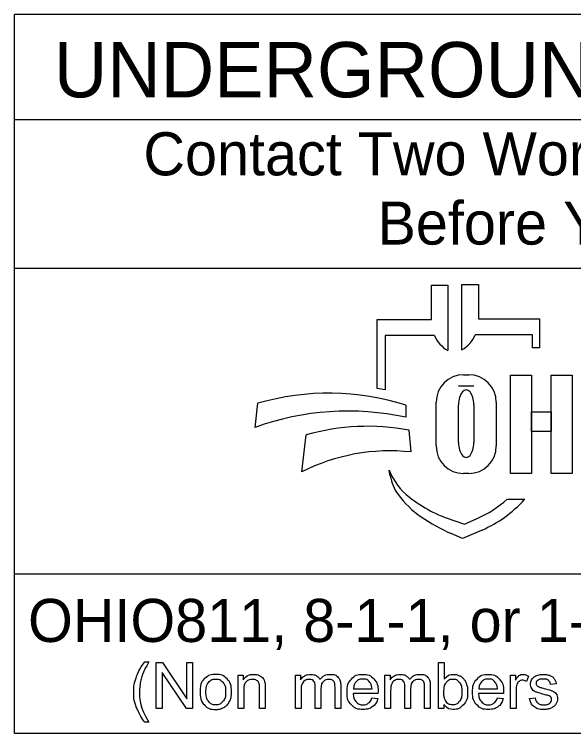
# Model space of a CAD drawing. Extents: x -4 to 116, y -17 to 29.
# Drawn here: x 50.861 to 52.679, y -12.463 to -10.125 of the extents above; entities that cross this region are included whole.
import ezdxf

# ---------------------------------------------------------------- set-up
doc = ezdxf.new("R2010")
doc.units = 0
doc.layers.add('SH_Data', color=7, linetype='Continuous')
doc.layers.add('SH_Text', color=7, linetype='Continuous')

msp = doc.modelspace()

# ---------------------------------------------------------------- linework, layer by layer
at = {"layer": 'SH_Data'}
for p, q in [((50.8608, -12.4625), (50.8608, -10.125)), ((55.1108, -10.125), (50.8608, -10.125)), ((50.8608, -10.4666), (55.1108, -10.4666)), ((50.8608, -10.95), (55.1108, -10.95)), ((55.1108, -11.9447), (50.8608, -11.9447)), ((55.1108, -12.4625), (50.8608, -12.4625))]:
    msp.add_line(p, q, dxfattribs=at)
at = {"layer": 'SH_Text'}
for p, q in [((52.2168, -11.117), (52.2168, -11.0055)), ((52.2168, -11.0055), (52.2705, -11.0055)), ((52.2705, -11.0055), (52.2705, -11.2176)), ((52.3161, -11.2153), (52.3161, -11.0032)), ((52.3161, -11.0032), (52.3698, -11.0032)), ((52.3698, -11.0032), (52.3698, -11.1147)), ((52.0409, -11.3409), (52.0409, -11.117)), ((52.0409, -11.117), (52.2168, -11.117)), ((52.3698, -11.1147), (52.569, -11.1147)), ((52.569, -11.1147), (52.569, -11.2085)), ((52.0661, -11.1685), (52.0661, -11.3453)), ((52.2272, -11.1685), (52.0661, -11.1685)), ((52.5457, -11.1661), (52.3594, -11.1661)), ((52.5457, -11.2085), (52.5457, -11.1661)), ((52.569, -11.2085), (52.5457, -11.2085)), ((52.3218, -11.2962), (52.3384, -11.2962)), ((52.3551, -11.3332), (52.3053, -11.3332)), ((51.6435, -11.4672), (51.6529, -11.3891)), ((52.1342, -11.3956), (52.1342, -11.4344)), ((52.2324, -11.5277), (52.2324, -11.3857)), ((52.3053, -11.5163), (52.3053, -11.394)), ((52.3551, -11.394), (52.3551, -11.5163)), ((52.4278, -11.3857), (52.4278, -11.5277)), ((52.1441, -11.4762), (52.1504, -11.5471)), ((51.7953, -11.6117), (51.81, -11.4916)), ((52.083, -11.6246), (52.08, -11.6067)), ((52.3384, -11.6172), (52.3218, -11.6172)), ((52.4633, -11.7005), (52.5207, -11.7005)), ((52.2649, -11.7609), (52.3243, -11.7814)), ((52.3243, -11.7814), (52.3653, -11.7636)), ((52.3816, -11.8009), (52.3183, -11.8284)), ((52.3183, -11.8284), (52.2809, -11.812))]:
    msp.add_line(p, q, dxfattribs=at)
for points in [[(52.4743, -11.2972), (52.5422, -11.2972), (52.5422, -11.6172), (52.4743, -11.6172)], [(52.6064, -11.2972), (52.6744, -11.2972), (52.6744, -11.6172), (52.6064, -11.6172)], [(52.5422, -11.4171), (52.6064, -11.4171), (52.6064, -11.4811), (52.5422, -11.4811)]]:
    msp.add_lwpolyline(points, close=True, dxfattribs=at)
for points in [[(51.2854, -12.2287), (51.2986, -12.2287)], [(51.3222, -12.3814), (51.3222, -12.2312), (51.3425, -12.2312), (51.4215, -12.3492), (51.4215, -12.2312), (51.4405, -12.2312), (51.4405, -12.3814), (51.4202, -12.3814), (51.3412, -12.2635), (51.3412, -12.3814), (51.3222, -12.3814)], [(52.2576, -12.3814), (52.2406, -12.3814), (52.2406, -12.2312), (52.259, -12.2312), (52.259, -12.2848)], [(51.5881, -12.3814), (51.5881, -12.2726), (51.6047, -12.2726), (51.6047, -12.288)], [(51.7745, -12.3814), (51.7745, -12.2726), (51.791, -12.2726), (51.791, -12.2879)], [(52.0659, -12.3814), (52.0659, -12.2726), (52.0824, -12.2726), (52.0824, -12.2879)], [(52.4737, -12.3814), (52.4737, -12.2726), (52.4903, -12.2726), (52.4903, -12.289)], [(52.5327, -12.276), (52.5263, -12.2931)], [(51.6765, -12.3145), (51.6765, -12.3814), (51.6581, -12.3814), (51.6581, -12.3153)], [(51.8576, -12.3182), (51.8576, -12.3814), (51.8392, -12.3814), (51.8392, -12.3107)], [(51.9221, -12.3067), (51.9221, -12.3814), (51.9036, -12.3814), (51.9036, -12.3129)], [(51.9632, -12.3166), (52.0239, -12.3166)], [(52.149, -12.3182), (52.149, -12.3814), (52.1306, -12.3814), (52.1306, -12.3107)], [(52.2134, -12.3067), (52.2134, -12.3814), (52.195, -12.3814), (52.195, -12.3129)], [(52.3711, -12.3166), (52.4319, -12.3166)], [(52.6227, -12.3007), (52.6046, -12.3031)], [(51.6066, -12.322), (51.6066, -12.3814), (51.5881, -12.3814)], [(51.793, -12.325), (51.793, -12.3814), (51.7745, -12.3814)], [(52.0433, -12.3317), (51.9621, -12.3317)], [(52.0843, -12.325), (52.0843, -12.3814), (52.0659, -12.3814)], [(52.4513, -12.3317), (52.3701, -12.3317)], [(52.4921, -12.3244), (52.4921, -12.3814), (52.4737, -12.3814)], [(52.0237, -12.3463), (52.0428, -12.3487)], [(52.4317, -12.3463), (52.4508, -12.3487)], [(52.5363, -12.3489), (52.5545, -12.346)], [(52.2576, -12.3678), (52.2576, -12.3814)], [(51.2986, -12.4256), (51.2854, -12.4256)]]:
    msp.add_lwpolyline(points, dxfattribs=at)
for centre, radius, start, end in [((52.3186, -11.1317), 0.0985, 201.9296, 240.7469), ((52.268, -11.1294), 0.0985, 299.2531, 338.0704), ((52.3218, -11.3857), 0.0895, 90, 180), ((52.3384, -11.3857), 0.0895, 0, 90), ((51.883, -12.1752), 0.8191, 72.1402, 106.3144), ((51.9127, -12.1499), 0.8191, 79.2074, 81.0007), ((51.946, -12.3063), 0.8919, 77.8238, 109.8274), ((52.01, -12.196), 0.7322, 79.44, 105.8467), ((52.082, -12.1792), 0.6357, 83.8248, 116.8021), ((52.3218, -11.5277), 0.0895, 180, 270), ((52.3384, -11.5277), 0.0895, 270, 0), ((52.2674, -11.5346), 0.2008, 201.0457, 232.5314), ((52.2243, -11.6005), 0.1433, 189.6817, 216.0884), ((52.358, -11.5031), 0.3088, 216.0884, 235.7167), ((52.4599, -11.2834), 0.5173, 232.5314, 241.794), ((52.2219, -11.4331), 0.3602, 293.4582, 312.0712), ((52.2219, -11.4331), 0.401, 293.4582, 317.8286), ((52.3747, -11.4422), 0.3371, 241.794, 250.9821), ((52.5245, -11.2588), 0.6044, 235.7167, 246.2325)]:
    msp.add_arc(centre, radius, start, end, dxfattribs=at)
for centre, start_param, end_param in [((52.3302, -11.394), 4.712389, 7.853982), ((52.3302, -11.5163), 1.570796, 4.712389)]:
    msp.add_ellipse(centre, major_axis=(0, 0.0484), ratio=0.514403, start_param=start_param, end_param=end_param, dxfattribs=at)
for points in [[(51.2854, -12.4256), (51.2701, -12.4063), (51.2596, -12.3805), (51.249, -12.3547), (51.249, -12.327), (51.249, -12.3027), (51.2569, -12.2803), (51.2661, -12.2544), (51.2854, -12.2287)], [(51.2986, -12.2287), (51.2862, -12.25), (51.2822, -12.2591), (51.276, -12.2733), (51.2724, -12.2886), (51.268, -12.3078), (51.268, -12.3271), (51.268, -12.3764), (51.2986, -12.4256)], [(51.4646, -12.327), (51.4646, -12.2968), (51.4814, -12.2822), (51.4955, -12.2702), (51.5156, -12.2702), (51.538, -12.2702), (51.5523, -12.2848), (51.5665, -12.2995), (51.5665, -12.3254), (51.5665, -12.3464), (51.5602, -12.3585), (51.5539, -12.3705), (51.5419, -12.3771), (51.5298, -12.3838), (51.5156, -12.3838), (51.4928, -12.3838), (51.4787, -12.3692), (51.4646, -12.3545), (51.4646, -12.327)], [(51.6047, -12.288), (51.6167, -12.2702), (51.6393, -12.2702), (51.6491, -12.2702), (51.6574, -12.2737), (51.6656, -12.2772), (51.6697, -12.283), (51.6738, -12.2887), (51.6755, -12.2966), (51.6765, -12.3017), (51.6765, -12.3145)], [(51.791, -12.2879), (51.7961, -12.2799), (51.8046, -12.275), (51.8131, -12.2702), (51.824, -12.2702), (51.8361, -12.2702), (51.8438, -12.2752), (51.8516, -12.2802), (51.8548, -12.2892), (51.8677, -12.2702), (51.8884, -12.2702), (51.9046, -12.2702), (51.9133, -12.2791), (51.9221, -12.2881), (51.9221, -12.3067)], [(52.0428, -12.3487), (52.0383, -12.3654), (52.0261, -12.3746), (52.0139, -12.3838), (51.9949, -12.3838), (51.9711, -12.3838), (51.9571, -12.3691), (51.9431, -12.3544), (51.9431, -12.3279), (51.9431, -12.3005), (51.9573, -12.2853), (51.9714, -12.2702), (51.9939, -12.2702), (52.0157, -12.2702), (52.0296, -12.285), (52.0434, -12.2999), (52.0434, -12.3268), (52.0434, -12.3284), (52.0433, -12.3317)], [(52.0824, -12.2879), (52.0875, -12.2799), (52.096, -12.275), (52.1045, -12.2702), (52.1154, -12.2702), (52.1275, -12.2702), (52.1352, -12.2752), (52.1429, -12.2802), (52.1461, -12.2892), (52.1591, -12.2702), (52.1798, -12.2702), (52.196, -12.2702), (52.2047, -12.2791), (52.2134, -12.2881), (52.2134, -12.3067)], [(52.259, -12.2848), (52.2707, -12.2702), (52.2888, -12.2702), (52.2988, -12.2702), (52.3078, -12.2742), (52.3167, -12.2782), (52.3225, -12.2856), (52.3283, -12.2929), (52.3316, -12.3032), (52.3349, -12.3136), (52.3349, -12.3253), (52.3349, -12.3533), (52.321, -12.3685), (52.3072, -12.3838), (52.2878, -12.3838), (52.2686, -12.3838), (52.2576, -12.3678)], [(52.4508, -12.3487), (52.4463, -12.3654), (52.4341, -12.3746), (52.4219, -12.3838), (52.4029, -12.3838), (52.3791, -12.3838), (52.3651, -12.3691), (52.3511, -12.3544), (52.3511, -12.3279), (52.3511, -12.3005), (52.3653, -12.2853), (52.3794, -12.2702), (52.4019, -12.2702), (52.4237, -12.2702), (52.4375, -12.285), (52.4514, -12.2999), (52.4514, -12.3268), (52.4514, -12.3284), (52.4513, -12.3317)], [(52.4903, -12.289), (52.4966, -12.2775), (52.502, -12.2738), (52.5074, -12.2702), (52.5138, -12.2702), (52.5231, -12.2702), (52.5327, -12.276)], [(52.5545, -12.346), (52.556, -12.357), (52.5631, -12.3628), (52.5701, -12.3687), (52.5827, -12.3687), (52.5955, -12.3687), (52.6017, -12.3635), (52.6078, -12.3583), (52.6078, -12.3514), (52.6078, -12.3451), (52.6024, -12.3415), (52.5986, -12.339), (52.5835, -12.3352), (52.5632, -12.3301), (52.5553, -12.3264), (52.5475, -12.3227), (52.5434, -12.3161), (52.5394, -12.3095), (52.5394, -12.3015), (52.5394, -12.2942), (52.5427, -12.288), (52.5461, -12.2818), (52.5518, -12.2777), (52.5561, -12.2746), (52.5635, -12.2724), (52.571, -12.2702), (52.5795, -12.2702), (52.5923, -12.2702), (52.602, -12.2738), (52.6117, -12.2775), (52.6163, -12.2838), (52.621, -12.2901), (52.6227, -12.3007)], [(51.4836, -12.327), (51.4836, -12.3479), (51.4927, -12.3583), (51.5018, -12.3687), (51.5156, -12.3687), (51.5293, -12.3687), (51.5384, -12.3582), (51.5475, -12.3478), (51.5475, -12.3264), (51.5475, -12.3062), (51.5384, -12.2958), (51.5292, -12.2854), (51.5156, -12.2854), (51.5018, -12.2854), (51.4927, -12.2957), (51.4836, -12.3061), (51.4836, -12.327)], [(51.6581, -12.3153), (51.6581, -12.304), (51.6559, -12.2984), (51.6537, -12.2928), (51.6483, -12.2895), (51.6428, -12.2862), (51.6354, -12.2862), (51.6236, -12.2862), (51.6151, -12.2937), (51.6066, -12.3011), (51.6066, -12.322)], [(51.8392, -12.3107), (51.8392, -12.2985), (51.8347, -12.2923), (51.8302, -12.2862), (51.8199, -12.2862), (51.8121, -12.2862), (51.8055, -12.2903), (51.7989, -12.2944), (51.7959, -12.3022), (51.793, -12.3101), (51.793, -12.325)], [(51.9036, -12.3129), (51.9036, -12.3018), (51.9018, -12.297), (51.9, -12.2921), (51.8953, -12.2891), (51.8906, -12.2862), (51.8843, -12.2862), (51.8728, -12.2862), (51.8652, -12.2938), (51.8576, -12.3014), (51.8576, -12.3182)], [(52.0239, -12.3166), (52.0227, -12.3028), (52.017, -12.296), (52.0081, -12.2853), (51.9941, -12.2853), (51.9814, -12.2853), (51.9727, -12.2938), (51.9641, -12.3023), (51.9632, -12.3166)], [(52.1306, -12.3107), (52.1306, -12.2985), (52.1261, -12.2923), (52.1215, -12.2862), (52.1113, -12.2862), (52.1035, -12.2862), (52.0969, -12.2903), (52.0903, -12.2944), (52.0873, -12.3022), (52.0843, -12.3101), (52.0843, -12.325)], [(52.195, -12.3129), (52.195, -12.3018), (52.1932, -12.297), (52.1914, -12.2921), (52.1867, -12.2891), (52.182, -12.2862), (52.1756, -12.2862), (52.1642, -12.2862), (52.1566, -12.2938), (52.149, -12.3014), (52.149, -12.3182)], [(52.2574, -12.3262), (52.2574, -12.3457), (52.2627, -12.3544), (52.2714, -12.3687), (52.2862, -12.3687), (52.2983, -12.3687), (52.3071, -12.3582), (52.3159, -12.3477), (52.3159, -12.3269), (52.3159, -12.3056), (52.3074, -12.2954), (52.299, -12.2853), (52.287, -12.2853), (52.275, -12.2853), (52.2662, -12.2958), (52.2574, -12.3063), (52.2574, -12.3262)], [(52.4319, -12.3166), (52.4307, -12.3028), (52.4249, -12.296), (52.4161, -12.2853), (52.4021, -12.2853), (52.3894, -12.2853), (52.3807, -12.2938), (52.3721, -12.3023), (52.3711, -12.3166)], [(52.5263, -12.2931), (52.5196, -12.2892), (52.5128, -12.2892), (52.5068, -12.2892), (52.502, -12.2928), (52.4972, -12.2964), (52.4952, -12.3029), (52.4921, -12.3127), (52.4921, -12.3244)], [(52.6046, -12.3031), (52.6034, -12.2947), (52.5975, -12.29), (52.5916, -12.2853), (52.5808, -12.2853), (52.5681, -12.2853), (52.5627, -12.2895), (52.5572, -12.2937), (52.5572, -12.2993), (52.5572, -12.3029), (52.5595, -12.3058), (52.5617, -12.3088), (52.5666, -12.3107), (52.5693, -12.3117), (52.5829, -12.3154), (52.6025, -12.3206), (52.6102, -12.324), (52.618, -12.3273), (52.6224, -12.3336), (52.6268, -12.34), (52.6268, -12.3494), (52.6268, -12.3586), (52.6214, -12.3668), (52.616, -12.3749), (52.6059, -12.3793), (52.5957, -12.3838), (52.5829, -12.3838), (52.5616, -12.3838), (52.5505, -12.375), (52.5394, -12.3662), (52.5363, -12.3489)], [(51.9621, -12.3317), (51.9632, -12.3496), (51.9723, -12.3592), (51.9814, -12.3687), (51.995, -12.3687), (52.0052, -12.3687), (52.0123, -12.3633), (52.0195, -12.358), (52.0237, -12.3463)], [(52.3701, -12.3317), (52.3711, -12.3496), (52.3803, -12.3592), (52.3894, -12.3687), (52.403, -12.3687), (52.4132, -12.3687), (52.4203, -12.3633), (52.4275, -12.358), (52.4317, -12.3463)]]:
    msp.add_open_spline(points, degree=3, dxfattribs=at)

# ---------------------------------------------------------------- texts
for s, height, p in [('UNDERGROUND UTILITIES', 0.18, (50.989, -10.3947)), ('Contact Two Working Days', 0.14, (51.2804, -10.6482)), ('Before You Dig', 0.14, (52.0416, -10.8732)), ('OHIO811, 8-1-1, or 1-800-362-2764', 0.14, (50.9053, -12.1647))]:
    msp.add_text(s, height=height, dxfattribs=at).set_placement(p)

doc.saveas('drawing.dxf')
